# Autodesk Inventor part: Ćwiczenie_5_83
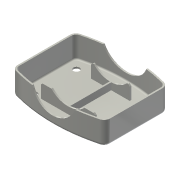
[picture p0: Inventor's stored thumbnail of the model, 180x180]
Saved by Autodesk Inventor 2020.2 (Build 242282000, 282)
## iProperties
Created: 2005-08
Part Number: Ćwiczenie_5_83
Document SubType Name: Modeling
Designer: F.Stasiak
Density: 1 g/cm^3
Material: Ogólny
Appearance: Gładkie — w kolorze kości słoniowej
Manager: www.cadconsulting.pl
Company: Fabian Stasiak CAD Consulting
Author: F.Stasiak
Subject: Zbiór ćwiczeń. Autodesk Inventor 2020. Kurs podstawowy
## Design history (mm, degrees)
sketch "Szkic1"
  geometry: L1 (-60, 40)-(60, 40); L2 (60, 40)-(60, -40); L3 (60, -40)-(-60, -40); L4 (-60, -40)-(-60, 40); L5 (0, 40)-(0, -40); A1 r 208.98 centre (0, -160.182) between (60, 40) and (-60, 40); A2 r 208.98 centre (0, 160.182) between (-60, -40) and (60, -40); 2 further points
  constraints: 10 end point, 4 point on circle, 3 midpoint, 2 centre point, 2 parallel, 1 coincident, 1 equal radius, 1 horizontal, 1 perpendicular
  dimensions: "d0" = 120 distance of L2.end L3.end; "d1" = 80 distance of L3.end L1.start
extrude "Wyciągnięcie proste1" new body sketch "Szkic1" distance "d2" = 30; taper "d3" = 0 deg
fillet "Zaokrąglenie1" dims "d4" = 8
fillet "Zaokrąglenie2" dims "d5" = 4
feature "Skorupa1" dims "d6" = 2
sketch "Szkic2"
  geometry: L1 (-45, 27.5)-(45, 27.5); L2 (45, 27.5)-(45, -27.5); L3 (45, -27.5)-(-45, -27.5); L4 (-45, -27.5)-(-45, 27.5); L5 (0, 27.5)-(0, -27.5); L6 (35, -28.5)-(-35, -28.5); L7 (-35, -28.5)-(-35, -26.5); L8 (-35, -26.5)-(35, -26.5); L9 (35, -26.5)-(35, -28.5); L10 (0, -28.5)-(0, -26.5); L11 (25, 26.5)-(-25, 26.5); L12 (-25, 26.5)-(-25, 28.5); L13 (-25, 28.5)-(25, 28.5); L14 (25, 28.5)-(25, 26.5); L15 (0, 26.5)-(0, 28.5); L16 (-1, 26.5)-(1, 26.5); L17 (1, 26.5)-(1, -26.5); L18 (1, -26.5)-(-1, -26.5); L19 (-1, -26.5)-(-1, 26.5); 2 further points
  constraints: 38 end point, 10 midpoint, 8 parallel, 4 horizontal, 4 perpendicular, 2 point on line, 1 coincident
  dimensions: "d7" = 90 distance of L2.end L3.end; "d8" = 55 distance of L3.end L1.start; "d16" = 2 distance of L6.end L7.end; "d17" = 2 distance of L11.end L12.end (= d16); "d18" = 50 distance of L12.end L13.end; "d19" = 70 distance of L7.end L8.end; "d28" = 2 distance between parallel lines of L17 L19 (= d17)
hole "Otwory1" sketch "Szkic2" diameter "d9" = 8; stored, may be unused: countersink angle "d13" = 90 deg, drill point angle "d15" = 118 deg; dims "d10" = 6, "d11" = 4, "d12" = 2, "d14" = 8
extrude "Wyciągnięcie proste2" join sketch "Szkic2" distance "d20" = 20; taper "d21" = 0 deg
sketch "Szkic3"
  geometry: C1 r 30 at (0, 40.881); 1 further point
  constraints: 1 centre point
  dimensions: "d25" = 60 diameter of C1
extrude "Wyciągnięcie proste3" cut sketch "Szkic3" extent not by distance; stored distance "d26" = 20; taper "d27" = 0 deg
chamfer "Faza1" distance "d22" = 2; stored, may be unused: second distance "d23" = 2, angle "d24" = 45 deg
node "Bryła1"
node "Korpusy bryłowe"
node "Korpusy powierzchniowe"
